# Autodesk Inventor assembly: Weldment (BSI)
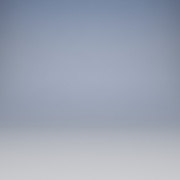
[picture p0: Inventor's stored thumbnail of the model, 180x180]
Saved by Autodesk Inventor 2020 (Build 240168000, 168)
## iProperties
Length Units: 11269
Angle Units: 11283
Time Units: 11279
Mass Units: 11290
Length Display Precision: 3
Angle Display Precision: 2
Part Number: Weldment (BSI)
Document SubType Name: Weldment
Created: 2002-06
Designer: smithga
Created: 2002-08
Weld Material: Welded Aluminum-6061
Manager: www.cadconsulting.pl
Company: Fabian Stasiak CAD Consulting
Control State: 0
Master: False
Shininess: 64.0
Angle Units: 11279
Time Units: 11290
Mass Units: 11283
Compacted: True
Density: 0.0
Volumn: 0.0
Area: 0.0
PropertySet Name: Model Information
Author: F.Stasiak
Subject: Zbiór ćwiczeń. Autodesk Inventor 2020. Kurs podstawowy
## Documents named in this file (1)
- M:\AUTOBUILD\M24_168_RTM\Application\App\Templates\en-US\Metric\Weldment (BSI).iam
